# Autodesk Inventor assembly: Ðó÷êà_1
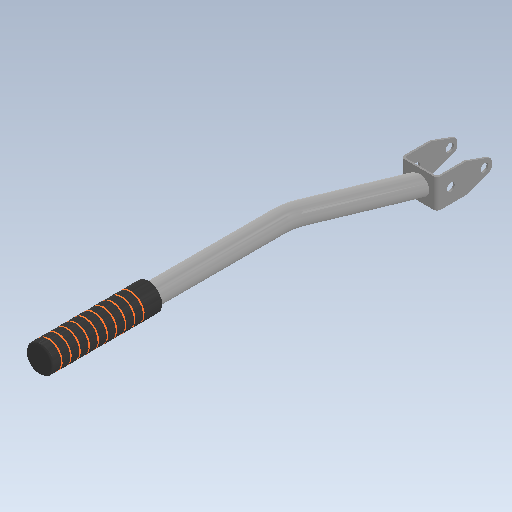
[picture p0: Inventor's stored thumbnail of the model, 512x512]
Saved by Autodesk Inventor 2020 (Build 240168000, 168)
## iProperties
Created: 1900-01
Part Number: Ðó÷êà_1
Document SubType Name: Assembly
Designer: bruno
Author: bruno
Revision Number: ANYUNSPECIFIED
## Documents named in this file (4)
- C:\Users\bruno\Downloads\Ðó÷êà_1.iam
- C:\Users\bruno\Downloads\Òðóáà ðó÷êè_1.ipt
- C:\Users\bruno\Downloads\Âèëêà ðó÷êè_1.ipt
- C:\Users\bruno\Downloads\HANDLE GRIP_1.ipt
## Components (3 placed, 3 different names)
1. 34
2. 35
3. 36
